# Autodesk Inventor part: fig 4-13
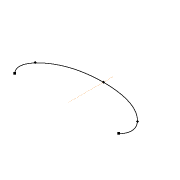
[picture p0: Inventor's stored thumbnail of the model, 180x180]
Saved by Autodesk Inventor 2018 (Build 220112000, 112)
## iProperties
Created: 2012-07
Part Number: fig 4-13
Material: Generic
Document SubType Name: Modeling
Designer: CADCIM
Density: 1 g/cm^3
Appearance: Default
Author: CADCIM
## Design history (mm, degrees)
sketch "Sketch1"
  geometry: L1 (0.121, 13.041)-(0.121, 1.483); L2 (-10.815, -1.576)-(-15.691, 3.573); L3 (-3.522, 10.439)-(3.764, 10.439); L4 (-14.873, 3.848)-(-11.149, 8.074); L5 (11.391, 8.074)-(15.115, 3.848); L6 (15.933, 3.573)-(11.057, -1.576); A1 r 5.401 centre (-9.332, 4.712) between (-14.53, 3.248) and (-11.076, -0.399); A2 r 30.439 centre (0.121, -20) between (3.022, 10.3) and (-2.78, 10.3); A3 r 7.63 centre (-7.286, 0.917) between (-11.348, 7.376) and (-14.205, 4.133); A4 r 7.63 centre (7.528, 0.917) between (14.447, 4.133) and (11.59, 7.376); A5 r 5.401 centre (9.574, 4.712) between (11.318, -0.399) and (14.772, 3.248); 5 further points
  constraints: 12 end point, 10 symmetric about line, 8 midpoint, 5 centre point, 5 point on circle, 1 vertical, 19 other
